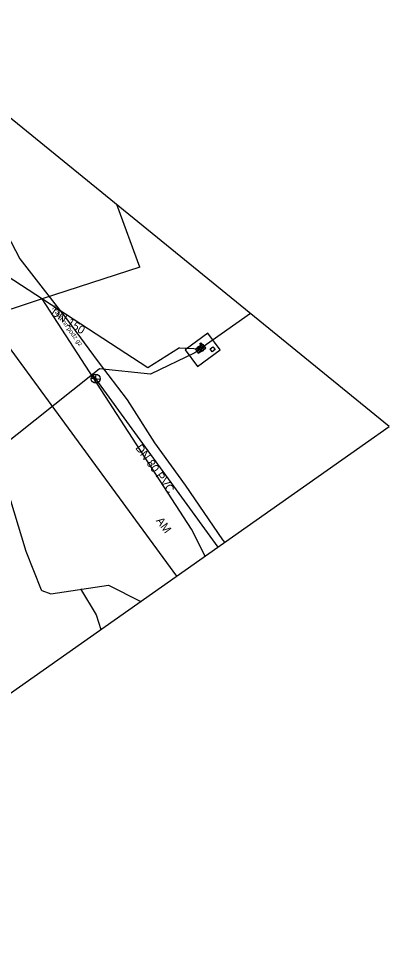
# Model space of a CAD drawing. Extents: x -492431 to -49223, y -1127123 to -112687.
# Drawn here: x -492173.9 to -492133, y -1127035 to -1126931.2 of the extents above; entities that cross this region are included whole.
import ezdxf

# ---------------------------------------------------------------- set-up
doc = ezdxf.new("R2010")
doc.units = 0
for name, color, linetype in [('Vrstva 1', 7, 'Continuous'), ('Vrstva 15', 7, 'Continuous'), ('Vrstva 19', 7, 'Continuous'), ('Vrstva 20', 7, 'Continuous'), ('Vrstva 22', 7, 'Continuous'), ('Vrstva 24', 7, 'Continuous'), ('Vrstva 26', 7, 'Continuous'), ('Vrstva 5', 7, 'Continuous'), ('Vrstva 9', 7, 'Continuous')]:
    doc.layers.add(name, color=color, linetype=linetype)

msp = doc.modelspace()

# ---------------------------------------------------------------- linework, layer by layer
at = {"layer": 'Vrstva 1'}
msp.add_line((-492154.86, -1126987.61), (-492171.35, -1126962.15), dxfattribs=at)
for points in [[(-492341.24, -1127122.91), (-492133.03, -1126976.26), (-492272.7, -1126862.46), (-492313.78, -1126867.2)], [(-492160.58, -1126958.63), (-492163.13, -1126951.73)], [(-492160.58, -1126958.63), (-492171.35, -1126962.15), (-492178.29, -1126964.42), (-492197.3, -1126970.63), (-492217.66, -1126977.28)], [(-492153.35, -1126990.58), (-492154.86, -1126987.61)]]:
    msp.add_lwpolyline(points, dxfattribs=at)
at = {"layer": 'Vrstva 15'}
msp.add_line((-492156.47, -1126992.78), (-492182.01, -1126957.94), dxfattribs=at)
at = {"layer": 'Vrstva 20'}
for p, q in [((-492156.18, -1126967.55), (-492153.85, -1126967.65)), ((-492165.82, -1126970.49), (-492195.9, -1126994.45)), ((-492165.04, -1126969.87), (-492165.82, -1126970.49)), ((-492165.44, -1126970.97), (-492165.82, -1126970.49)), ((-492159.41, -1126970.45), (-492165.04, -1126969.87))]:
    msp.add_line(p, q, dxfattribs=at)
for points in [[(-492156.18, -1126967.55), (-492159.7, -1126969.78), (-492178.64, -1126957.41), (-492180.67, -1126957.3), (-492181.99, -1126957.75)], [(-492148.36, -1126963.77), (-492153.2, -1126967.18), (-492153.85, -1126967.65)], [(-492153.85, -1126967.65), (-492154.5, -1126968.12), (-492159.41, -1126970.45)], [(-492151.93, -1126989.58), (-492165.44, -1126970.97)]]:
    msp.add_lwpolyline(points, dxfattribs=at)
at = {"layer": 'Vrstva 22'}
for p, q in [((-492153.85, -1126967.3), (-492153.85, -1126967.15)), ((-492165.5, -1126971.46), (-492165.39, -1126970.48)), ((-492165.93, -1126970.91), (-492164.95, -1126971.02))]:
    msp.add_line(p, q, dxfattribs=at)
for points in [[(-492155.57, -1126967.76), (-492154.22, -1126969.61), (-492151.71, -1126967.79), (-492153.06, -1126965.93)], [(-492153.43, -1126967.38), (-492154.41, -1126967.71), (-492154.14, -1126968.13)], [(-492154, -1126967.15), (-492153.85, -1126967), (-492153.7, -1126967.15), (-492153.83, -1126967.15)]]:
    msp.add_lwpolyline(points, close=True, dxfattribs=at)
for points in [[(-492153.56, -1126967.17), (-492154.41, -1126967.71), (-492154.14, -1126968.13), (-492153.29, -1126967.59), (-492153.56, -1126967.17)], [(-492152.82, -1126967.67), (-492152.5, -1126967.43), (-492152.26, -1126967.75), (-492152.58, -1126967.99), (-492152.82, -1126967.67)]]:
    msp.add_lwpolyline(points, dxfattribs=at)
for centre, radius in [((-492153.85, -1126967.65), 0.35), ((-492165.44, -1126970.97), 0.5), ((-492165.44, -1126970.97), 0.025)]:
    msp.add_circle(centre, radius, dxfattribs=at)
at = {"layer": 'Vrstva 26'}
for p, q in [((-492176.77, -1126978.18), (-492173.17, -1126990.02)), ((-492173.17, -1126990.02), (-492171.49, -1126994.3)), ((-492171.49, -1126994.3), (-492171.39, -1126994.37)), ((-492171.39, -1126994.37), (-492170.42, -1126994.74)), ((-492170.42, -1126994.74), (-492164.03, -1126993.78)), ((-492167.12, -1126994.2), (-492165.4, -1126997.05)), ((-492164.03, -1126993.78), (-492160.45, -1126995.58)), ((-492165.4, -1126997.05), (-492164.89, -1126998.7))]:
    msp.add_line(p, q, dxfattribs=at)
at = {"layer": 'Vrstva 5'}
msp.add_lwpolyline([(-492187.72, -1126931.69), (-492187.22, -1126932.95), (-492184.4, -1126938.94), (-492183.02, -1126941.61), (-492179.72, -1126947.62), (-492176.25, -1126953.11), (-492173.84, -1126957.71), (-492168.67, -1126964.36), (-492165.18, -1126969.1), (-492161.99, -1126973.32), (-492158.94, -1126978.07), (-492155.57, -1126982.75), (-492151.44, -1126988.78), (-492151.19, -1126989.06)], dxfattribs=at)

# ---------------------------------------------------------------- texts
at = {"layer": 'Vrstva 19'}
msp.add_text('AM', height=0.91, rotation=306.2441, dxfattribs=at).set_placement((-492158.83, -1126986.67))
at = {"layer": 'Vrstva 24'}
for s, rotation, p in [('DN 150', 326.8508, (-492170.46, -1126963.84)), ('DN 80 PVC', 305.9842, (-492161.11, -1126978.63))]:
    msp.add_text(s, height=0.91, rotation=rotation, dxfattribs=at).set_placement(p)
at = {"layer": 'Vrstva 9'}
msp.add_text('Trasa nn podz gz', height=0.5, rotation=306.3728, dxfattribs=at).set_placement((-492170.39, -1126963.12))

doc.saveas('drawing.dxf')
